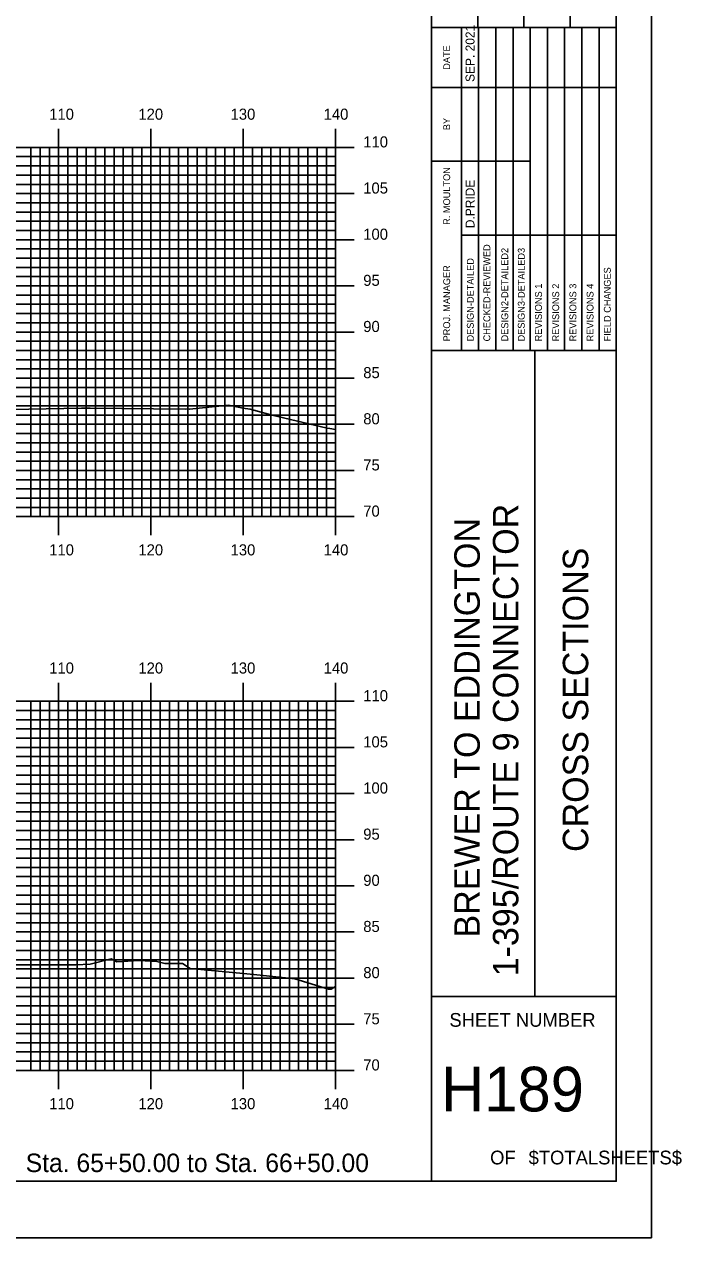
# Model space of a CAD drawing. Extents: x 1759036 to 1759380, y 442591 to 442811.
# Drawn here: x 1759308.4 to 1759379.7, y 442590.5 to 442722 of the extents above; entities that cross this region are included whole.
import ezdxf

# ---------------------------------------------------------------- set-up
doc = ezdxf.new("R2010")
doc.units = 0
for name, color, linetype in [('BORDER', 7, 'Continuous'), ('H_V ANNOTATION', 7, 'Continuous'), ('MAJOR', 7, 'Continuous'), ('MINOR', 7, 'Continuous'), ('PLOT BOUNDARY', 7, 'Continuous'), ('S_Roadway_Centerline', 7, 'Continuous')]:
    doc.layers.add(name, color=color, linetype=linetype)

msp = doc.modelspace()

# ---------------------------------------------------------------- linework, layer by layer
at = {"layer": 'BORDER'}
for p, q in [((1759352.56, 442596.67), (1759352.56, 442806.67)), ((1759357.56, 442721.67), (1759357.56, 442738.97)), ((1759362.56, 442721.67), (1759362.56, 442738.97)), ((1759367.56, 442721.67), (1759367.56, 442738.97)), ((1759352.56, 442721.67), (1759372.56, 442721.67)), ((1759352.56, 442686.67), (1759372.56, 442686.67)), ((1759363.74, 442616.67), (1759363.74, 442686.67)), ((1759352.56, 442616.67), (1759372.56, 442616.67))]:
    msp.add_line(p, q, dxfattribs=at)
msp.add_lwpolyline([(1759052.56, 442596.67), (1759372.56, 442596.67), (1759372.56, 442806.67), (1759052.56, 442806.67)], close=True, dxfattribs=at)
for points in [[(1759355.79, 442715.17), (1759355.79, 442721.67)], [(1759357.66, 442686.68), (1759357.66, 442721.67)], [(1759359.52, 442721.67), (1759359.52, 442686.68)], [(1759361.38, 442686.68), (1759361.38, 442721.67)], [(1759363.25, 442686.68), (1759363.25, 442721.67)], [(1759365.11, 442686.68), (1759365.11, 442721.67)], [(1759366.97, 442686.68), (1759366.97, 442721.67)], [(1759368.84, 442686.68), (1759368.84, 442721.67)], [(1759370.7, 442686.68), (1759370.7, 442721.67)], [(1759355.79, 442686.68), (1759355.79, 442720.26)], [(1759352.56, 442715.17), (1759372.56, 442715.17)], [(1759352.56, 442707.17), (1759355.79, 442707.17)], [(1759355.79, 442707.17), (1759363.24, 442707.17)], [(1759355.79, 442699.17), (1759372.56, 442699.17)]]:
    msp.add_lwpolyline(points, dxfattribs=at)
at = {"layer": 'MAJOR'}
for p, q in [((1759312.16, 442710.67), (1759312.16, 442708.67)), ((1759322.16, 442710.67), (1759322.16, 442708.67)), ((1759332.16, 442710.67), (1759332.16, 442708.67)), ((1759342.16, 442710.67), (1759342.16, 442708.67)), ((1759062.16, 442708.67), (1759342.16, 442708.67)), ((1759062.16, 442708.67), (1759342.16, 442708.67)), ((1759312.16, 442668.67), (1759312.16, 442708.67)), ((1759322.16, 442668.67), (1759322.16, 442708.67)), ((1759332.16, 442668.67), (1759332.16, 442708.67)), ((1759344.17, 442708.67), (1759340.16, 442708.67)), ((1759342.16, 442668.67), (1759342.16, 442708.67)), ((1759342.16, 442668.67), (1759342.16, 442708.67)), ((1759062.16, 442703.67), (1759342.16, 442703.67)), ((1759344.17, 442703.67), (1759340.16, 442703.67)), ((1759062.16, 442698.67), (1759342.16, 442698.67)), ((1759344.17, 442698.67), (1759340.16, 442698.67)), ((1759062.16, 442693.67), (1759342.16, 442693.67)), ((1759344.17, 442693.67), (1759340.16, 442693.67)), ((1759062.16, 442688.67), (1759342.16, 442688.67)), ((1759344.17, 442688.67), (1759340.16, 442688.67)), ((1759062.16, 442683.67), (1759342.16, 442683.67)), ((1759344.17, 442683.67), (1759340.16, 442683.67)), ((1759062.16, 442678.67), (1759342.16, 442678.67)), ((1759344.17, 442678.67), (1759340.16, 442678.67)), ((1759062.16, 442673.67), (1759342.16, 442673.67)), ((1759344.17, 442673.67), (1759340.16, 442673.67)), ((1759062.16, 442668.67), (1759342.16, 442668.67)), ((1759062.16, 442668.67), (1759342.16, 442668.67)), ((1759312.16, 442666.66), (1759312.16, 442668.67)), ((1759322.16, 442666.66), (1759322.16, 442668.67)), ((1759332.16, 442666.66), (1759332.16, 442668.67)), ((1759344.17, 442668.67), (1759340.16, 442668.67)), ((1759342.16, 442666.66), (1759342.16, 442668.67)), ((1759312.16, 442650.67), (1759312.16, 442648.67)), ((1759322.16, 442650.67), (1759322.16, 442648.67)), ((1759332.16, 442650.67), (1759332.16, 442648.67)), ((1759342.16, 442650.67), (1759342.16, 442648.67)), ((1759062.16, 442648.67), (1759342.16, 442648.67)), ((1759062.16, 442648.67), (1759342.16, 442648.67)), ((1759312.16, 442608.67), (1759312.16, 442648.67)), ((1759322.16, 442608.67), (1759322.16, 442648.67)), ((1759332.16, 442608.67), (1759332.16, 442648.67)), ((1759344.17, 442648.67), (1759340.16, 442648.67)), ((1759342.16, 442608.67), (1759342.16, 442648.67)), ((1759342.16, 442608.67), (1759342.16, 442648.67)), ((1759062.16, 442643.67), (1759342.16, 442643.67)), ((1759344.17, 442643.67), (1759340.16, 442643.67)), ((1759062.16, 442638.67), (1759342.16, 442638.67)), ((1759344.17, 442638.67), (1759340.16, 442638.67)), ((1759062.16, 442633.67), (1759342.16, 442633.67)), ((1759344.17, 442633.67), (1759340.16, 442633.67)), ((1759062.16, 442628.67), (1759342.16, 442628.67)), ((1759344.17, 442628.67), (1759340.16, 442628.67)), ((1759062.16, 442623.67), (1759342.16, 442623.67)), ((1759344.17, 442623.67), (1759340.16, 442623.67)), ((1759062.16, 442618.67), (1759342.16, 442618.67)), ((1759344.17, 442618.67), (1759340.16, 442618.67)), ((1759062.16, 442613.67), (1759342.16, 442613.67)), ((1759344.17, 442613.67), (1759340.16, 442613.67)), ((1759062.16, 442608.67), (1759342.16, 442608.67)), ((1759062.16, 442608.67), (1759342.16, 442608.67)), ((1759312.16, 442606.66), (1759312.16, 442608.67)), ((1759322.16, 442606.66), (1759322.16, 442608.67)), ((1759332.16, 442606.66), (1759332.16, 442608.67)), ((1759344.17, 442608.67), (1759340.16, 442608.67)), ((1759342.16, 442606.66), (1759342.16, 442608.67))]:
    msp.add_line(p, q, dxfattribs=at)
at = {"layer": 'MINOR'}
for p, q in [((1759309.16, 442668.67), (1759309.16, 442708.67)), ((1759310.16, 442668.67), (1759310.16, 442708.67)), ((1759311.16, 442668.67), (1759311.16, 442708.67)), ((1759313.16, 442668.67), (1759313.16, 442708.67)), ((1759314.16, 442668.67), (1759314.16, 442708.67)), ((1759315.16, 442668.67), (1759315.16, 442708.67)), ((1759316.16, 442668.67), (1759316.16, 442708.67)), ((1759317.16, 442668.67), (1759317.16, 442708.67)), ((1759318.16, 442668.67), (1759318.16, 442708.67)), ((1759319.16, 442668.67), (1759319.16, 442708.67)), ((1759320.16, 442668.67), (1759320.16, 442708.67)), ((1759321.16, 442668.67), (1759321.16, 442708.67)), ((1759323.16, 442668.67), (1759323.16, 442708.67)), ((1759324.16, 442668.67), (1759324.16, 442708.67)), ((1759325.16, 442668.67), (1759325.16, 442708.67)), ((1759326.16, 442668.67), (1759326.16, 442708.67)), ((1759327.16, 442668.67), (1759327.16, 442708.67)), ((1759328.16, 442668.67), (1759328.16, 442708.67)), ((1759329.16, 442668.67), (1759329.16, 442708.67)), ((1759330.16, 442668.67), (1759330.16, 442708.67)), ((1759331.16, 442668.67), (1759331.16, 442708.67)), ((1759333.16, 442668.67), (1759333.16, 442708.67)), ((1759334.16, 442668.67), (1759334.16, 442708.67)), ((1759335.16, 442668.67), (1759335.16, 442708.67)), ((1759336.16, 442668.67), (1759336.16, 442708.67)), ((1759337.16, 442668.67), (1759337.16, 442708.67)), ((1759338.16, 442668.67), (1759338.16, 442708.67)), ((1759339.16, 442668.67), (1759339.16, 442708.67)), ((1759340.16, 442668.67), (1759340.16, 442708.67)), ((1759341.16, 442668.67), (1759341.16, 442708.67)), ((1759062.16, 442707.67), (1759342.16, 442707.67)), ((1759342.16, 442707.67), (1759340.16, 442707.67)), ((1759062.16, 442706.67), (1759342.16, 442706.67)), ((1759062.16, 442705.67), (1759342.16, 442705.67)), ((1759342.16, 442706.67), (1759340.16, 442706.67)), ((1759342.16, 442705.67), (1759340.16, 442705.67)), ((1759062.16, 442704.67), (1759342.16, 442704.67)), ((1759342.16, 442704.67), (1759340.16, 442704.67)), ((1759062.16, 442702.67), (1759342.16, 442702.67)), ((1759062.16, 442701.67), (1759342.16, 442701.67)), ((1759342.16, 442702.67), (1759340.16, 442702.67)), ((1759342.16, 442701.67), (1759340.16, 442701.67)), ((1759062.16, 442700.67), (1759342.16, 442700.67)), ((1759342.16, 442700.67), (1759340.16, 442700.67)), ((1759062.16, 442699.67), (1759342.16, 442699.67)), ((1759342.16, 442699.67), (1759340.16, 442699.67)), ((1759062.16, 442697.67), (1759342.16, 442697.67)), ((1759342.16, 442697.67), (1759340.16, 442697.67)), ((1759062.16, 442696.67), (1759342.16, 442696.67)), ((1759342.16, 442696.67), (1759340.16, 442696.67)), ((1759062.16, 442695.67), (1759342.16, 442695.67)), ((1759342.16, 442695.67), (1759340.16, 442695.67)), ((1759062.16, 442694.67), (1759342.16, 442694.67)), ((1759342.16, 442694.67), (1759340.16, 442694.67)), ((1759062.16, 442692.67), (1759342.16, 442692.67)), ((1759342.16, 442692.67), (1759340.16, 442692.67)), ((1759062.16, 442691.67), (1759342.16, 442691.67)), ((1759342.16, 442691.67), (1759340.16, 442691.67)), ((1759062.16, 442690.67), (1759342.16, 442690.67)), ((1759342.16, 442690.67), (1759340.16, 442690.67)), ((1759062.16, 442689.67), (1759342.16, 442689.67)), ((1759342.16, 442689.67), (1759340.16, 442689.67)), ((1759062.16, 442687.67), (1759342.16, 442687.67)), ((1759342.16, 442687.67), (1759340.16, 442687.67)), ((1759062.16, 442686.67), (1759342.16, 442686.67)), ((1759342.16, 442686.67), (1759340.16, 442686.67)), ((1759062.16, 442685.67), (1759342.16, 442685.67)), ((1759062.16, 442684.67), (1759342.16, 442684.67)), ((1759342.16, 442685.67), (1759340.16, 442685.67)), ((1759342.16, 442684.67), (1759340.16, 442684.67)), ((1759062.16, 442682.67), (1759342.16, 442682.67)), ((1759342.16, 442682.67), (1759340.16, 442682.67)), ((1759062.16, 442681.67), (1759342.16, 442681.67)), ((1759062.16, 442680.67), (1759342.16, 442680.67)), ((1759342.16, 442681.67), (1759340.16, 442681.67)), ((1759342.16, 442680.67), (1759340.16, 442680.67)), ((1759062.16, 442679.67), (1759342.16, 442679.67)), ((1759342.16, 442679.67), (1759340.16, 442679.67)), ((1759062.16, 442677.67), (1759342.16, 442677.67)), ((1759062.16, 442676.67), (1759342.16, 442676.67)), ((1759342.16, 442677.67), (1759340.16, 442677.67)), ((1759342.16, 442676.67), (1759340.16, 442676.67)), ((1759062.16, 442675.67), (1759342.16, 442675.67)), ((1759342.16, 442675.67), (1759340.16, 442675.67)), ((1759062.16, 442674.67), (1759342.16, 442674.67)), ((1759342.16, 442674.67), (1759340.16, 442674.67)), ((1759062.16, 442672.67), (1759342.16, 442672.67)), ((1759342.16, 442672.67), (1759340.16, 442672.67)), ((1759062.16, 442671.67), (1759342.16, 442671.67)), ((1759342.16, 442671.67), (1759340.16, 442671.67)), ((1759062.16, 442670.67), (1759342.16, 442670.67)), ((1759342.16, 442670.67), (1759340.16, 442670.67)), ((1759062.16, 442669.67), (1759342.16, 442669.67)), ((1759342.16, 442669.67), (1759340.16, 442669.67)), ((1759062.16, 442647.67), (1759342.16, 442647.67)), ((1759309.16, 442608.67), (1759309.16, 442648.67)), ((1759310.16, 442608.67), (1759310.16, 442648.67)), ((1759311.16, 442608.67), (1759311.16, 442648.67)), ((1759313.16, 442608.67), (1759313.16, 442648.67)), ((1759314.16, 442608.67), (1759314.16, 442648.67)), ((1759315.16, 442608.67), (1759315.16, 442648.67)), ((1759316.16, 442608.67), (1759316.16, 442648.67)), ((1759317.16, 442608.67), (1759317.16, 442648.67)), ((1759318.16, 442608.67), (1759318.16, 442648.67)), ((1759319.16, 442608.67), (1759319.16, 442648.67)), ((1759320.16, 442608.67), (1759320.16, 442648.67)), ((1759321.16, 442608.67), (1759321.16, 442648.67)), ((1759323.16, 442608.67), (1759323.16, 442648.67)), ((1759324.16, 442608.67), (1759324.16, 442648.67)), ((1759325.16, 442608.67), (1759325.16, 442648.67)), ((1759326.16, 442608.67), (1759326.16, 442648.67)), ((1759327.16, 442608.67), (1759327.16, 442648.67)), ((1759328.16, 442608.67), (1759328.16, 442648.67)), ((1759329.16, 442608.67), (1759329.16, 442648.67)), ((1759330.16, 442608.67), (1759330.16, 442648.67)), ((1759331.16, 442608.67), (1759331.16, 442648.67)), ((1759333.16, 442608.67), (1759333.16, 442648.67)), ((1759334.16, 442608.67), (1759334.16, 442648.67)), ((1759335.16, 442608.67), (1759335.16, 442648.67)), ((1759336.16, 442608.67), (1759336.16, 442648.67)), ((1759337.16, 442608.67), (1759337.16, 442648.67)), ((1759338.16, 442608.67), (1759338.16, 442648.67)), ((1759339.16, 442608.67), (1759339.16, 442648.67)), ((1759340.16, 442608.67), (1759340.16, 442648.67)), ((1759342.16, 442647.67), (1759340.16, 442647.67)), ((1759341.16, 442608.67), (1759341.16, 442648.67)), ((1759062.16, 442646.67), (1759342.16, 442646.67)), ((1759342.16, 442646.67), (1759340.16, 442646.67)), ((1759062.16, 442645.67), (1759342.16, 442645.67)), ((1759342.16, 442645.67), (1759340.16, 442645.67)), ((1759062.16, 442644.67), (1759342.16, 442644.67)), ((1759342.16, 442644.67), (1759340.16, 442644.67)), ((1759062.16, 442642.67), (1759342.16, 442642.67)), ((1759342.16, 442642.67), (1759340.16, 442642.67)), ((1759062.16, 442641.67), (1759342.16, 442641.67)), ((1759342.16, 442641.67), (1759340.16, 442641.67)), ((1759062.16, 442640.67), (1759342.16, 442640.67)), ((1759342.16, 442640.67), (1759340.16, 442640.67)), ((1759062.16, 442639.67), (1759342.16, 442639.67)), ((1759342.16, 442639.67), (1759340.16, 442639.67)), ((1759062.16, 442637.67), (1759342.16, 442637.67)), ((1759342.16, 442637.67), (1759340.16, 442637.67)), ((1759062.16, 442636.67), (1759342.16, 442636.67)), ((1759342.16, 442636.67), (1759340.16, 442636.67)), ((1759062.16, 442635.67), (1759342.16, 442635.67)), ((1759062.16, 442634.67), (1759342.16, 442634.67)), ((1759342.16, 442635.67), (1759340.16, 442635.67)), ((1759342.16, 442634.67), (1759340.16, 442634.67)), ((1759062.16, 442632.67), (1759342.16, 442632.67)), ((1759342.16, 442632.67), (1759340.16, 442632.67)), ((1759062.16, 442631.67), (1759342.16, 442631.67)), ((1759062.16, 442630.67), (1759342.16, 442630.67)), ((1759342.16, 442631.67), (1759340.16, 442631.67)), ((1759342.16, 442630.67), (1759340.16, 442630.67)), ((1759062.16, 442629.67), (1759342.16, 442629.67)), ((1759342.16, 442629.67), (1759340.16, 442629.67)), ((1759062.16, 442627.67), (1759342.16, 442627.67)), ((1759062.16, 442626.67), (1759342.16, 442626.67)), ((1759342.16, 442627.67), (1759340.16, 442627.67)), ((1759342.16, 442626.67), (1759340.16, 442626.67)), ((1759062.16, 442625.67), (1759342.16, 442625.67)), ((1759342.16, 442625.67), (1759340.16, 442625.67)), ((1759062.16, 442624.67), (1759342.16, 442624.67)), ((1759342.16, 442624.67), (1759340.16, 442624.67)), ((1759062.16, 442622.67), (1759342.16, 442622.67)), ((1759342.16, 442622.67), (1759340.16, 442622.67)), ((1759062.16, 442621.67), (1759342.16, 442621.67)), ((1759342.16, 442621.67), (1759340.16, 442621.67)), ((1759062.16, 442620.67), (1759342.16, 442620.67)), ((1759342.16, 442620.67), (1759340.16, 442620.67)), ((1759062.16, 442619.67), (1759342.16, 442619.67)), ((1759342.16, 442619.67), (1759340.16, 442619.67)), ((1759062.16, 442617.67), (1759342.16, 442617.67)), ((1759342.16, 442617.67), (1759340.16, 442617.67)), ((1759062.16, 442616.67), (1759342.16, 442616.67)), ((1759342.16, 442616.67), (1759340.16, 442616.67)), ((1759062.16, 442615.67), (1759342.16, 442615.67)), ((1759342.16, 442615.67), (1759340.16, 442615.67)), ((1759062.16, 442614.67), (1759342.16, 442614.67)), ((1759342.16, 442614.67), (1759340.16, 442614.67)), ((1759062.16, 442612.67), (1759342.16, 442612.67)), ((1759342.16, 442612.67), (1759340.16, 442612.67)), ((1759062.16, 442611.67), (1759342.16, 442611.67)), ((1759342.16, 442611.67), (1759340.16, 442611.67)), ((1759062.16, 442610.67), (1759342.16, 442610.67)), ((1759062.16, 442609.67), (1759342.16, 442609.67)), ((1759342.16, 442610.67), (1759340.16, 442610.67)), ((1759342.16, 442609.67), (1759340.16, 442609.67))]:
    msp.add_line(p, q, dxfattribs=at)
at = {"layer": 'PLOT BOUNDARY'}
msp.add_lwpolyline([(1759036.37, 442590.55), (1759376.37, 442590.55), (1759376.37, 442810.55), (1759036.37, 442810.55)], close=True, dxfattribs=at)
at = {"layer": 'S_Roadway_Centerline'}
for points in [[(1759232.15, 442679.87), (1759243.01, 442680.13), (1759248.75, 442680.22), (1759263.06, 442680.24), (1759270.52, 442680.23), (1759274.03, 442680.25), (1759298.56, 442680.27), (1759303.25, 442680.22), (1759305.08, 442680.23), (1759314.63, 442680.42), (1759315.58, 442680.43), (1759325.85, 442680.31), (1759326.2, 442680.36), (1759326.32, 442680.31), (1759330.55, 442680.76), (1759331.96, 442680.45), (1759332.11, 442680.41), (1759332.91, 442680.32), (1759335.29, 442679.67), (1759341.26, 442678.25), (1759341.54, 442678.2), (1759342.16, 442678.1)], [(1759306.02, 442620.11), (1759314.02, 442620.1), (1759315.56, 442620.19), (1759317.86, 442620.76), (1759318.46, 442620.44), (1759320.88, 442620.59), (1759322.78, 442620.46), (1759323.67, 442620.25), (1759325.59, 442620.24), (1759326.41, 442619.73), (1759333.31, 442619.07), (1759337.74, 442618.58), (1759341.38, 442617.49), (1759341.68, 442617.46), (1759342.16, 442617.78)]]:
    msp.add_lwpolyline(points, dxfattribs=at)

# ---------------------------------------------------------------- texts
at = {"layer": 'BORDER'}
for s, height, p in [('SEP. 2021', 0.969, (1759357.21, 442715.76)), ('DATE', 0.743, (1759354.57, 442717.08)), ('BY', 0.743, (1759354.57, 442710.54)), ('R. MOULTON', 0.745, (1759354.57, 442700.28)), ('D.PRIDE', 0.969, (1759357.21, 442699.92)), ('CHECKED-REVIEWED', 0.7455, (1759358.92, 442687.65)), ('DESIGN2-DETAILED2', 0.7455, (1759360.86, 442687.65)), ('DESIGN3-DETAILED3', 0.7455, (1759362.65, 442687.65)), ('DESIGN-DETAILED', 0.7455, (1759357.13, 442687.65)), ('PROJ. MANAGER', 0.7455, (1759354.57, 442687.65)), ('FIELD CHANGES', 0.7455, (1759371.97, 442687.65)), ('REVISIONS 1', 0.7455, (1759364.51, 442687.65)), ('REVISIONS 2', 0.7455, (1759366.38, 442687.65)), ('REVISIONS 3', 0.7455, (1759368.24, 442687.65)), ('REVISIONS 4', 0.7455, (1759370.1, 442687.65)), ('1-395/ROUTE 9 CONNECTOR', 2.7557, (1759361.96, 442618.87)), ('BREWER TO EDDINGTON', 2.7557, (1759357.78, 442623.07)), ('CROSS SECTIONS', 2.7557, (1759369.53, 442632.34))]:
    msp.add_text(s, height=height, rotation=90, dxfattribs=at).set_placement(p)
for s, height, p in [('SHEET NUMBER', 1.4905, (1759354.49, 442613.4)), ('H189', 4.839, (1759353.59, 442604.23)), ('OF', 1.491, (1759358.9, 442598.49)), ('$TOTALSHEETS$', 1.4905, (1759363.07, 442598.49))]:
    msp.add_text(s, height=height, dxfattribs=at).set_placement(p)
at = {"layer": 'H_V ANNOTATION'}
for s, height, p in [('110', 1.2, (1759311.14, 442711.67)), ('120', 1.2, (1759320.8, 442711.67)), ('130', 1.2, (1759330.79, 442711.67)), ('140', 1.2, (1759340.87, 442711.67)), ('110', 1.2, (1759345.16, 442708.67)), ('105', 1.2, (1759345.16, 442703.67)), ('100', 1.2, (1759345.16, 442698.67)), ('95', 1.2, (1759345.16, 442693.67)), ('90', 1.2, (1759345.16, 442688.67)), ('85', 1.2, (1759345.16, 442683.67)), ('80', 1.2, (1759345.16, 442678.67)), ('75', 1.2, (1759345.16, 442673.67)), ('70', 1.2, (1759345.16, 442668.67)), ('110', 1.2, (1759311.14, 442664.47)), ('120', 1.2, (1759320.8, 442664.47)), ('130', 1.2, (1759330.79, 442664.47)), ('140', 1.2, (1759340.87, 442664.47)), ('110', 1.2, (1759311.14, 442651.67)), ('120', 1.2, (1759320.8, 442651.67)), ('130', 1.2, (1759330.79, 442651.67)), ('140', 1.2, (1759340.87, 442651.67)), ('110', 1.2, (1759345.16, 442648.67)), ('105', 1.2, (1759345.16, 442643.67)), ('100', 1.2, (1759345.16, 442638.67)), ('95', 1.2, (1759345.16, 442633.67)), ('90', 1.2, (1759345.16, 442628.67)), ('85', 1.2, (1759345.16, 442623.67)), ('80', 1.2, (1759345.16, 442618.67)), ('75', 1.2, (1759345.16, 442613.67)), ('70', 1.2, (1759345.16, 442608.67)), ('110', 1.2, (1759311.14, 442604.47)), ('120', 1.2, (1759320.8, 442604.47)), ('130', 1.2, (1759330.79, 442604.47)), ('140', 1.2, (1759340.87, 442604.47)), ('Sta. 65+50.00 to Sta. 66+50.00', 2.0004, (1759308.59, 442597.66))]:
    msp.add_text(s, height=height, dxfattribs=at).set_placement(p)

doc.saveas('drawing.dxf')
